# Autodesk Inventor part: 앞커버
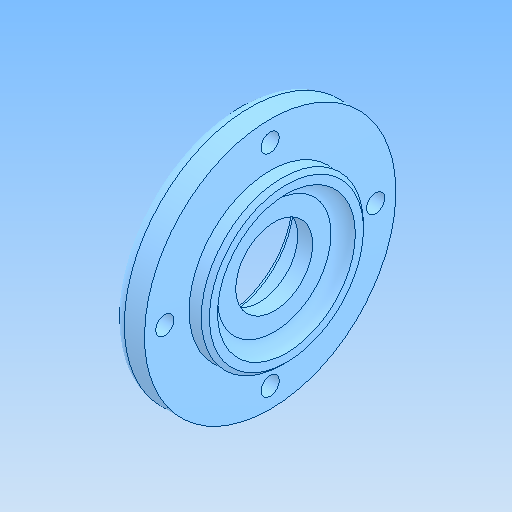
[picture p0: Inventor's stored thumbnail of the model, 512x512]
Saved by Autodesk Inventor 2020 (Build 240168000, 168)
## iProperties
Created: 2024-09
Part Number: 앞커버
Material: 알루미늄 6061
Document SubType Name: Modeling
Designer: oem
Density: 2.7 g/cm^3
Appearance: 기본값
Author: jhkim
Sending System: Autodesk Inventor 2025
Preprocessor: ST-DEVELOPER v20
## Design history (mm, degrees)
feature "솔리드1"
node "솔리드2"
